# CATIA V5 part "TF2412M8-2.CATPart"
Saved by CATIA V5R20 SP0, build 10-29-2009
Part number: TF2412M8-2
Revision: ANY
Definition: UNKNOWN
Nomenclature: TF2412M8-2
Source: Unknown
Bounding box of the stored display mesh (mm): x -5.703 to 5.703, y 0 to 4.95, z -5.85 to 5.85
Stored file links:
  C:\Users\Utente\Desktop\IO LAVORO\3D X SITO CF\CUMSA\3D files RCM\RCM 245712\TF2412M8-2.CATPart
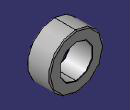
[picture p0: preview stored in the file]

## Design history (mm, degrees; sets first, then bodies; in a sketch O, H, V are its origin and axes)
Body1 "Chaflán2" (main body)
  Solid1: solid without history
